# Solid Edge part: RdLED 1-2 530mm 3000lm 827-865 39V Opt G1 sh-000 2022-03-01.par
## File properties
Author: jaroslaw.przewlocki
Template: iso metric part.par
Last saved by: jaroslaw.przewlocki
Revision: 3
Application: Solid Edge
Gęstość: 0,000 kg/m^3
Dokładność: 0,990
Username: jaroslaw.przewlocki
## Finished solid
Body 1: solid body, 4156 faces, 10818 edges, 7090 vertices, 3 separate solids.
  Faces by surface: plane 3657, cylinder 231, spline 160, cone 52, torus 22, sphere 20, spun 14
  Edges by curve: line 9734, curve on surface 564, circle 300, ellipse 132, spline 76, intersection 12
Bounding box of the edges (mm; curved faces can reach further): 529.996 x 4.500 x 265.000, from (-264.9981, -4.5, -132.5) to (264.9981, 0, 132.5).
Cylindrical faces by radius (mm): R0.2 x78, R0.2002 x4, R0.2169 x6, R0.25 x24, R0.3 x4, R0.3373 x6, R0.4 x16, R0.4006 x4, R0.4008 x4, R0.525 x4, R0.6 x24, R1 x16, R1.0894 x4, R1.1 x28, R2.1 x8, R265 x1
Conical faces (half-angle, radius in mm at the cone's reference point): 0.5 deg R0.5056 x8, 0.5 deg R1.0082 x8, 1 deg R0.5511 x4, 10 deg R0.2132 x4, 10 deg R0.4132 x4, 18.4844 deg R1.0657 x8, 27.363 deg R0.6214 x4, 45 deg R0.575 x4, 45 deg R0.625 x8
Toroidal faces (ring radius, tube radius in mm): R0.1 r0.2 x2, R0.8 r0.2 x8, R0.8522 r0.3 x4, R0.9002 r0.2 x2, R0.9018 r0.2 x2, R1.3 r0.2 x4
Spherical faces by radius (mm): R0.2 x16, R0.6 x4
Planar faces by outward normal: +x 48, +y 23, +z 47, -x 48, -y 663, -z 48, oblique 2780
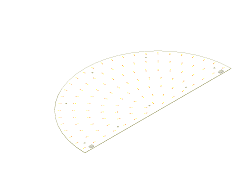
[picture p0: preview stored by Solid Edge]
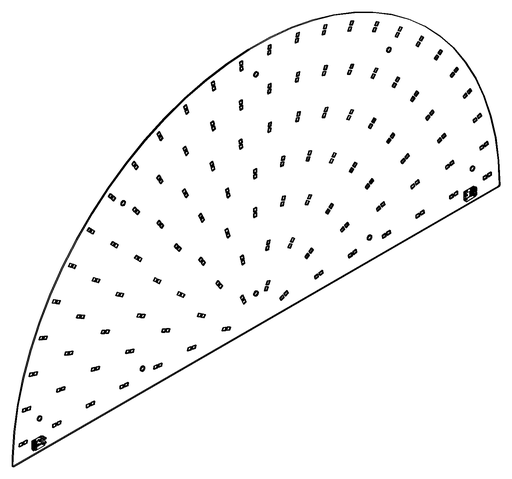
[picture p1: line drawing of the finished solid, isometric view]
